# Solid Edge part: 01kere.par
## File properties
Author: User
Template: Iso Metric Part.par
Last saved by: User
Revision: 81
Application: Solid Edge
Accuracy: 0,990
Username: User
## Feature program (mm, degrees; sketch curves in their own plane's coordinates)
make body feature "unnamed MakeBodyFeature 1"
sketch for "unnamed RevolvedCutout 1" plane through (0, 0, 0) normal (0, -1, 0) x-axis (1, 0, 0)
revolve "unnamed RevolvedCutout 1" cut finite 360 deg
thinwall "Thinwall_5"  Thickness = 3 mm
web network "WebNetwork_5"  Profile_Plane1_Distance = 37.4985 mm; Thickness = 3 mm
web network "WebNetwork_7"  Profile_Plane1_Distance = 0.011 mm; Thickness = 3 mm
web network "WebNetwork_8"  Profile_Plane1_Distance = 37.4985 mm; Thickness = 3 mm
web network "WebNetwork_9"  Profile_Plane1_Distance = 0.01 mm; Thickness = 3 mm
web network "WebNetwork_10"  Profile_Plane1_Distance = 0.01 mm; Thickness = 3 mm
fillet "Round_1" radius 1.5
chamfer "Chamfer_1" setback 1.5
sketch for "ExtrudedCutout_1" plane through (101.2072, 0, 37.4985) normal (0, 0, 1) x-axis (0, -1, 0)
extrude "ExtrudedCutout_1" cut through along -normal  FiniteDepth2 = 26.2885 mm
sketch for "ExtrudedCutout_2" plane through (-34.4128, -1.2347, 24.0931) normal (1, 0, 0) x-axis (0, 1, 0)
  line (11.2347, -3.315) -> (-8.7653, -3.315)
  line (-8.7653, -3.315) -> (-8.7653, 8.685)
  line (-8.7653, 8.685) -> (11.2347, 8.685)
  line (11.2347, 8.685) -> (11.2347, -3.315)
extrude "ExtrudedCutout_2" cut through along -normal  FiniteDepth2 = 0.2251 mm
sketch for "ExtrudedProtrusion_17" plane through (0, 0, 45.5448) normal (0, 0, 1) x-axis (1, 0, 0)
  circle centre (-119.461, -1.0597) radius 0.75
extrude "ExtrudedProtrusion_17" add through along -normal  Profile_Plane1_Distance = 45.5448 mm
pattern "Pattern_2" of "ExtrudedProtrusion_17"  XDirCount = 15; XDirSpacing = 16.7535 mm
extrude "unnamed Protrusion 1" add through
extrude "unnamed Protrusion 2" add through
extrude "unnamed Protrusion 3" add through
extrude "unnamed Protrusion 4" add through
extrude "unnamed Protrusion 5" add through
extrude "unnamed Protrusion 6" add through
swept protrusion "SweptProtrusion_6"
mirror "unnamed Mirror 1" of "ExtrudedProtrusion_17", "SweptProtrusion_6", "Pattern_2"
pattern "unnamed Pattern 1"
sketch for "ExtrudedCutout_4" plane through (26.6042, 0.2649, 20.7781) normal (0, 0, 1) x-axis (0, 1, 0)
extrude "ExtrudedCutout_4" cut through along -normal  FiniteDepth2 = 4.6552 mm
chamfer "Chamfer_2" setback 1
sketch used by "unnamed Protrusion 7" plane through (0, -34.7659, 0) normal (0, -1, 0) x-axis (1, 0, 0)
extrude "unnamed Protrusion 7" add along -normal
rib "Rib_17"  Thickness = 2 mm
mirror "unnamed Mirror 2" of "Rib_17" about plane through (0, 0, 0) normal (0, -1, 0)
rib "unnamed Rib 1"
sketch for "ExtrudedProtrusion_37" plane through (-77.0537, 0, 39.4985) normal (0, 0, 1) x-axis (0, -1, 0)
  line (-8.6314, 35.7509) -> (8.6314, 35.7509)
  line (8.6314, 35.7509) -> (8.6314, 24.8406)
  line (8.6314, 24.8406) -> (-8.6314, 24.8406)
  line (-8.6314, 24.8406) -> (-8.6314, 35.7509)
extrude "ExtrudedProtrusion_37" add through along -normal  Profile_Plane1_Distance = 2 mm
draft "Draft_1"  Angles1 = 45 deg
chamfer "Chamfer_3" setback 0.5
sketch for "ExtrudedProtrusion_38" plane through (-46.7579, 0, 39.4985) normal (0, 0, 1) x-axis (0, 1, 0)
  circle centre (-6.9108, 3.8873) radius 0.5
extrude "ExtrudedProtrusion_38" add finite 0.5 along +normal
logasc func "Lip_Groove_2"  LipOrGrooveWidth = 0.35 mm; LipOrGrooveHeight = 0.1 mm
pattern "unnamed Pattern 2" of "Lip_Groove_2", "ExtrudedProtrusion_38"
pattern "unnamed Pattern 3"
fillet "Round_4" radius 0.15
fillet "Round_5" radius 0.15
sketch for "ExtrudedProtrusion_47" plane through (-37.4128, -0.1295, 24.8277) normal (-1, 0, 0) x-axis (0, 1, 0)
  line (-11.1165, -8.243) -> (11.9517, -8.243)
  line (11.9517, -8.243) -> (11.9517, 5.6006)
  line (11.9517, 5.6006) -> (-11.1165, 5.6006)
  line (-11.1165, 5.6006) -> (-11.1165, -8.243)
extrude "ExtrudedProtrusion_47" add finite 1 along -normal
Other named dimensions: "KeypointCurve_1": Curve_Length = 249.6056 mm | "KeypointCurve_4": StartDerivMagnitude = 111.121 mm | "KeypointCurve_9": StartDerivMagnitude = -21.3254 mm; EndDerivMagnitude = -20.5439 mm | "OffsetSurface_1": Distance = 1 mm | "OffsetSurface_2": Distance = 0.1 mm
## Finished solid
Body 1: sheet body, 1 face, 4 edges, 4 vertices.
  Faces by surface: offset 1
  Edges by curve: curve on surface 4
Body 2: sheet body, 2 faces, 8 edges, 7 vertices.
  Faces by surface: offset 2
  Edges by curve: curve on surface 8
Body 3: sheet body, 1 face, 2 edges, 2 vertices.
  Faces by surface: sphere 1
  Edges by curve: circle 2
Body 4: sheet body, 1 face, 2 edges, 2 vertices.
  Faces by surface: plane 1
  Edges by curve: circle 1, line 1
Body 5: sheet body, 1 face, 2 edges, 2 vertices.
  Faces by surface: plane 1
  Edges by curve: circle 1, line 1
Body 6: solid body, 195 faces, 423 edges, 241 vertices.
  Faces by surface: plane 86, cylinder 46, swept 37, offset 10, torus 9, spline 6, spun 1
  Edges by curve: intersection 202, line 160, circle 57, curve on surface 2, spline 2
Body 7: solid body, 4 faces, 7 edges, 5 vertices.
  Faces by surface: spline 3, plane 1
  Edges by curve: curve on surface 4, spline 3
Bounding box of the edges (mm; curved faces can reach further): 245.063 x 62.176 x 38.272, from (-128.0841, -31.5533, 8.0228) to (116.9792, 30.6232, 46.2948).
Cylindrical faces by radius (mm): R0.0913 x1, R0.1122 x2, R0.1276 x1, R0.1824 x3, R0.2742 x1, R0.4 x9, R0.5 x9, R0.5076 x1, R0.75 x14, R0.8702 x1, R1.5 x1, R1.6164 x1, R1.6909 x1, R2.3 x1
Toroidal faces (ring radius, tube radius in mm): R0.25 r0.15 x9
Spherical faces by radius (mm): R0.75 x1
Planar faces by outward normal: +x 7, +y 5, +z 29, -x 6, -y 5, -z 6, oblique 29
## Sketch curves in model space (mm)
line (86.0715, 6.6824, 20.7781) -> (87.6112, 6.6824, 22.3178)
spline (102.2025, -34.7659, 32.3036) -> (101.6072, -34.7659, 33.9946) -> (101.0119, -34.7659, 35.6856)
spline (99.8315, -34.7659, 32.3036) -> (101.017, -34.7659, 32.3036) -> (102.2025, -34.7659, 32.3036)
spline (101.0067, -34.7659, 35.6856) -> (100.4191, -34.7659, 33.9946) -> (99.8315, -34.7659, 32.3036)
spline (101.0119, -34.7659, 35.6856) -> (101.0093, -34.7659, 35.6856) -> (101.0067, -34.7659, 35.6856)
spline (101.6585, -34.7659, 36.4297) -> (102.8004, -34.7659, 33.271) -> (103.9422, -34.7659, 30.1123)
spline (100.5089, -34.7659, 36.5272) -> (101.0915, -34.7659, 36.6243) -> (101.6585, -34.7659, 36.4297)
spline (98.1226, -34.7659, 29.9275) -> (99.2726, -34.7659, 33.2427) -> (100.5089, -34.7659, 36.5272)
spline (98.1585, -34.7659, 29.8197) -> (98.129, -34.7659, 29.8659) -> (98.1226, -34.7659, 29.9275)
spline (99.0053, -34.7659, 29.8608) -> (98.5997, -34.7659, 29.7582) -> (98.1585, -34.7659, 29.8197)
spline (99.6057, -34.7659, 31.58) -> (99.3112, -34.7659, 30.7179) -> (99.0053, -34.7659, 29.8608)
spline (102.4386, -34.7659, 31.58) -> (101.0221, -34.7659, 31.58) -> (99.6057, -34.7659, 31.58)
spline (103.0236, -34.7659, 29.9224) -> (102.7311, -34.7659, 30.7512) -> (102.4386, -34.7659, 31.58)
spline (103.0698, -34.7659, 29.8454) -> (103.0467, -34.7659, 29.88) -> (103.0236, -34.7659, 29.9224)
spline (103.1416, -34.7659, 29.7941) -> (103.098, -34.7659, 29.814) -> (103.0698, -34.7659, 29.8454)
spline (103.9422, -34.7659, 30.1123) -> (103.7266, -34.7659, 29.7609) -> (103.1416, -34.7659, 29.7941)
spline (97.6479, -34.7659, 30.5485) -> (97.7374, -34.7659, 30.3857) -> (97.7506, -34.7659, 30.1841)
spline (95.1282, -34.7659, 30.5741) -> (96.3908, -34.7659, 30.5741) -> (97.6479, -34.7659, 30.5485)
spline (95.1076, -34.7659, 36.5272) -> (95.1282, -34.7659, 33.5524) -> (95.1282, -34.7659, 30.5741)
spline (95.0306, -34.7659, 36.5785) -> (95.0768, -34.7659, 36.5548) -> (95.1076, -34.7659, 36.5272)
spline (94.3122, -34.7659, 36.5785) -> (94.6714, -34.7659, 36.6247) -> (95.0306, -34.7659, 36.5785)
spline (94.2352, -34.7659, 36.5272) -> (94.266, -34.7659, 36.5548) -> (94.3122, -34.7659, 36.5785)
spline (97.6479, -34.7659, 29.8095) -> (94.2147, -34.7659, 31.5103) -> (94.2352, -34.7659, 36.5272)
spline (97.7403, -34.7659, 30.0045) -> (97.7137, -34.7659, 29.8952) -> (97.6479, -34.7659, 29.8095)
spline (97.7506, -34.7659, 30.1841) -> (97.7493, -34.7659, 30.0847) -> (97.7403, -34.7659, 30.0045)
spline (93.1139, -34.7659, 30.3637) -> (93.121, -34.7659, 30.2816) -> (93.1242, -34.7659, 30.1841)
spline (93.0216, -34.7659, 30.5485) -> (93.078, -34.7659, 30.4818) -> (93.1139, -34.7659, 30.3637)
spline (90.4966, -34.7659, 30.5741) -> (91.7616, -34.7659, 30.5741) -> (93.0216, -34.7659, 30.5485)
spline (90.3991, -34.7659, 36.5785) -> (90.4966, -34.7659, 33.5995) -> (90.4966, -34.7659, 30.5741)
spline (89.6806, -34.7659, 36.5785) -> (90.08, -34.7659, 36.6243) -> (90.3991, -34.7659, 36.5785)
spline (89.6037, -34.7659, 36.5272) -> (89.6345, -34.7659, 36.5548) -> (89.6806, -34.7659, 36.5785)
spline (93.0216, -34.7659, 29.8095) -> (89.5831, -34.7659, 31.5079) -> (89.6037, -34.7659, 36.5272)
spline (93.1139, -34.7659, 30.0045) -> (93.0829, -34.7659, 29.8971) -> (93.0216, -34.7659, 29.8095)
spline (93.1242, -34.7659, 30.1841) -> (93.121, -34.7659, 30.0847) -> (93.1139, -34.7659, 30.0045)
spline (88.4106, -34.7659, 36.4554) -> (87.4336, -34.7659, 34.4355) -> (86.4091, -34.7659, 32.437)
spline (87.5638, -34.7659, 36.5837) -> (88.1173, -34.7659, 36.62) -> (88.4106, -34.7659, 36.4554)
spline (87.4406, -34.7659, 36.44) -> (87.4868, -34.7659, 36.5272) -> (87.5638, -34.7659, 36.5837)
spline (85.9831, -34.7659, 33.2889) -> (86.6873, -34.7659, 34.8756) -> (87.4406, -34.7659, 36.44)
spline (85.9729, -34.7659, 33.2889) -> (85.978, -34.7659, 33.2889) -> (85.9831, -34.7659, 33.2889)
spline (84.4435, -34.7659, 36.5323) -> (85.2317, -34.7659, 34.9219) -> (85.9729, -34.7659, 33.2889)
spline (84.3563, -34.7659, 36.5837) -> (84.4057, -34.7659, 36.5599) -> (84.4435, -34.7659, 36.5323)
spline (85.5007, -34.7659, 32.437) -> (84.275, -34.7659, 34.8722) -> (84.3563, -34.7659, 36.5837)
spline (85.5213, -34.7659, 29.8557) -> (85.5007, -34.7659, 31.1442) -> (85.5007, -34.7659, 32.437)
spline (86.3167, -34.7659, 29.8043) -> (85.8996, -34.7659, 29.759) -> (85.5213, -34.7659, 29.8557)
spline (86.3886, -34.7659, 29.8557) -> (86.3603, -34.7659, 29.8242) -> (86.3167, -34.7659, 29.8043)
spline (86.4091, -34.7659, 32.437) -> (86.4091, -34.7659, 31.1442) -> (86.3886, -34.7659, 29.8557)
spline (82.8501, -34.7659, 31.1438) -> (82.906, -34.7659, 31.0283) -> (82.922, -34.7659, 30.7589)
spline (82.7321, -34.7659, 35.2391) -> (78.9346, -34.7659, 33.1933) -> (82.8501, -34.7659, 31.1438)
spline (82.804, -34.7659, 35.2596) -> (82.77, -34.7659, 35.2417) -> (82.7321, -34.7659, 35.2391)
spline (82.8861, -34.7659, 35.4546) -> (82.8574, -34.7659, 35.3498) -> (82.804, -34.7659, 35.2596)
spline (82.8655, -34.7659, 30.4202) -> (78.0026, -34.7659, 33.5677) -> (82.8861, -34.7659, 35.4546)
spline (82.8963, -34.7659, 30.5074) -> (82.8829, -34.7659, 30.4599) -> (82.8655, -34.7659, 30.4202)
spline (82.922, -34.7659, 30.7589) -> (82.9169, -34.7659, 30.6152) -> (82.8963, -34.7659, 30.5074)
spline (76.5713, -34.7659, 36.1115) -> (74.0457, -34.7659, 34.44) -> (76.9716, -34.7659, 31.698)
spline (76.5456, -34.7659, 36.1834) -> (76.5584, -34.7659, 36.1532) -> (76.5713, -34.7659, 36.1115)
spline (76.4789, -34.7659, 36.2655) -> (76.5199, -34.7659, 36.2187) -> (76.5456, -34.7659, 36.1834)
spline (72.8762, -34.7659, 31.0155) -> (73.7648, -34.7659, 33.3923) -> (76.4789, -34.7659, 36.2655)
spline (76.9716, -34.7659, 31.698) -> (74.9661, -34.7659, 29.7068) -> (72.8762, -34.7659, 31.0155)
circle centre (-119.461, -1.0597, 45.5448) radius 0.75
spline (-46.8252, 0, 8.9817) -> (-50.3731, -15.9175, 21.2405) -> (-51.7511, -22.574, 40.5904)
line (-143.3647, 0, 50.1271) -> (-143.3647, 0, -4.8306)
spline (117.0345, 0, 47.2772) -> (106.613, 0, 26.0225) -> (90.8029, 0, 2.0674)
spline (116.9792, -17.5729, 39.6959) -> (116.9792, -13.8775, 23.0797) -> (116.9792, 0, 13.1797)
spline (0, -30.0639, 40.2417) -> (0, -21.6111, 19.922) -> (0, 0, 10.1179)
spline (-127.7662, 0, 41.1979) -> (-111.7262, 0, 21.0489) -> (-82.9183, 0, 10.1179)
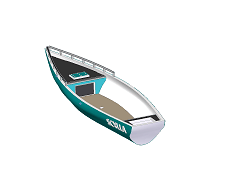
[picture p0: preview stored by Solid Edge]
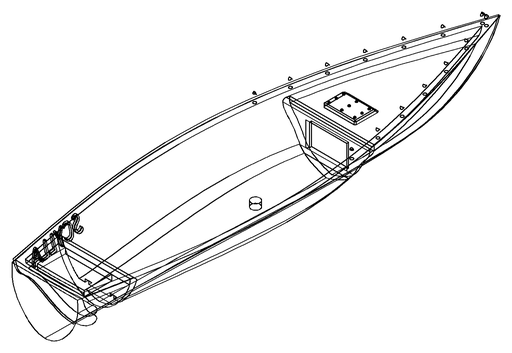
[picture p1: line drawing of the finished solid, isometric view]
